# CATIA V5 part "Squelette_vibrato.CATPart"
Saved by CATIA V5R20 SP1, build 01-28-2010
Part number: Squelette_vibrato
Publications: "Droite.1", "Plan.7", "Plan.1", "Plan.2", "Plan.3", "Plan.4", "Plan.5", "Plan.6", "Point.1", "Plan.8", "Plan.9"
Bounding box of the stored display mesh (mm): x -20 to 20, y 1 to 1, z 35 to 35
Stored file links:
  F:\Pro\Emplois\1_Chercheur\ThinkMOTION\MMS\MMS_GR1\abruchon\Catia\Squelette_vibrato.CATPart
  F:\Pro\Emplois\1_Chercheur\ThinkMOTION\MMS\MMS_GR1\abruchon\Catia\Vibrato.CATProduct
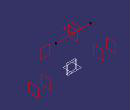
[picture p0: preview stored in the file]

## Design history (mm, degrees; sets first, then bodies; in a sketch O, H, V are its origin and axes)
External parameters (linked from other documents)
  External.Longueur_bati = 30 mm
  External.Hauteur_vibrato = 40 mm
  External.Largeur_vibrato = 90 mm
  External.largeur_chevalet = 60 mm
  External.decalage_axe = 5 mm
Set1 "Set_vibrato"
  Plane1: type Offset, RefPlane zx-plane, Offset 2, reversed
  Plane2: type Offset, RefPlane Plane1, Offset 30 {= External.Longueur_bati}, reversed
  Plane3: type Offset, RefPlane xy-plane, Offset 40 {= External.Hauteur_vibrato}
  Plane4: type Offset, RefPlane xy-plane, Offset 0
  Plane5: type Offset, RefPlane yz-plane, Offset 45 {= External.Largeur_vibrato /2}
  Plane6: type Offset, RefPlane yz-plane, Offset 45 {= External.Largeur_vibrato /2}, reversed
  Plane7: type Offset, RefPlane yz-plane, Offset 30 {= External.largeur_chevalet /2}
  Plane8: type Offset, RefPlane yz-plane, Offset 30 {= External.largeur_chevalet /2}, reversed
  Point1: (0, 1, 35 {= External.Hauteur_vibrato -External.decalage_axe})
  Line1: type PtDir, RefPoint Point1, Direction Plane7, Start -20, End 20
  Plane9: type Normal, Curve Line1
Body1 (main body)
